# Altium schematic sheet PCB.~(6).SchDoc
size A2
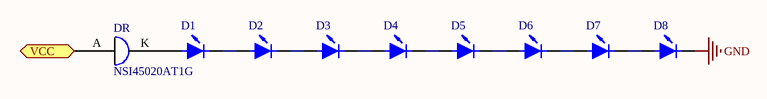
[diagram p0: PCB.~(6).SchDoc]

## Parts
D1  LED0  [UV_LED]  (value not drawn)
D2  LED0  [UV_LED]  (value not drawn)
D3  LED0  [UV_LED]  (value not drawn)
D4  LED0  [UV_LED]  (value not drawn)
D5  LED0  [UV_LED]  (value not drawn)
D6  LED0  [UV_LED]  (value not drawn)
D7  LED0  [UV_LED]  (value not drawn)
D8  LED0  [UV_LED]  (value not drawn)
DR  NSI45020AT1G  [NSI45020AT1G]

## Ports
VCC

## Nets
GND: D8.2(K)
VCC: DR.A ; port VCC
NetD1_1: D1.1(A) DR.K
NetD1_2: D1.2(K) D2.1(A)
NetD2_2: D2.2(K) D3.1(A)
NetD3_2: D3.2(K) D4.1(A)
NetD4_2: D4.2(K) D5.1(A)
NetD5_2: D5.2(K) D6.1(A)
NetD6_2: D6.2(K) D7.1(A)
NetD7_2: D7.2(K) D8.1(A)

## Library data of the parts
D1-D8 = LED0: Typical INFRARED GaAs LED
